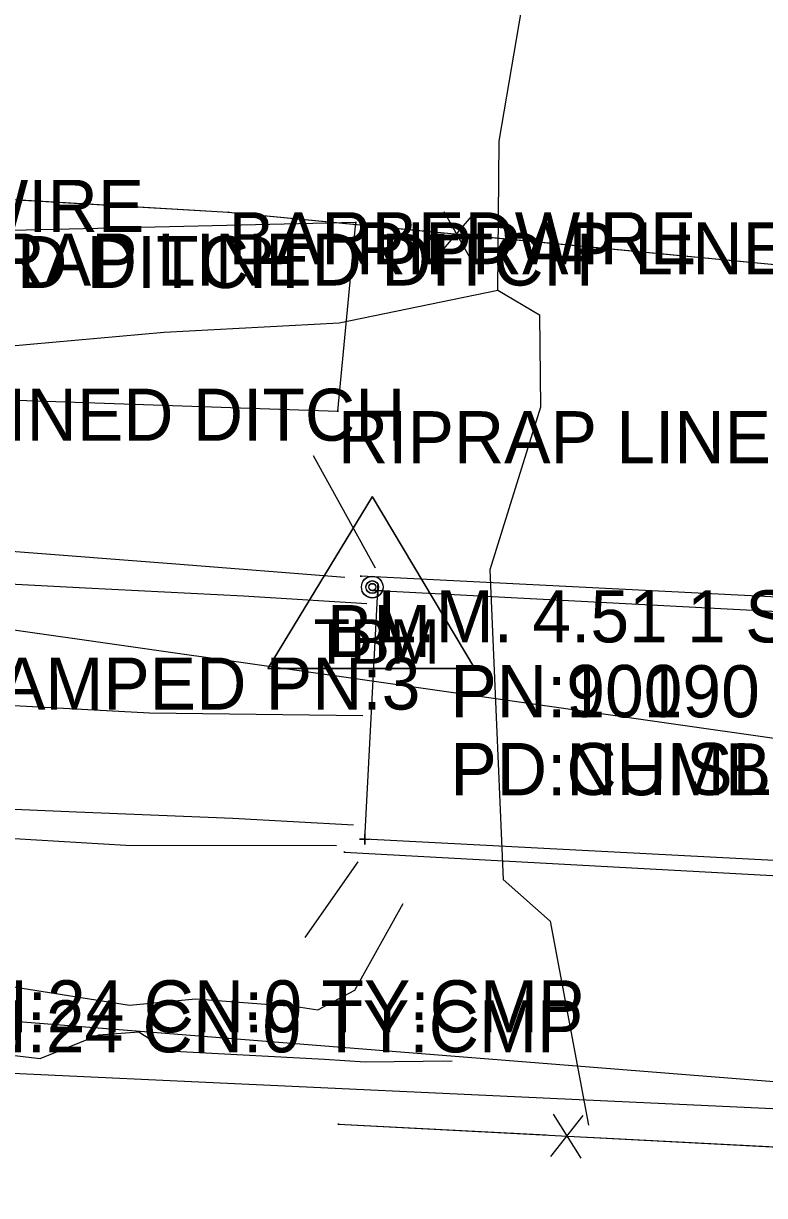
# Model space of a CAD drawing. Extents: x 675481 to 678499, y 212715 to 215285.
# Drawn here: x 676966.8 to 677038, y 214637 to 214749.7 of the extents above; entities that cross this region are included whole.
import ezdxf

# ---------------------------------------------------------------- set-up
doc = ezdxf.new("R2010")
doc.units = 0
for name, color, linetype in [('S_BASELINE', 7, 'Continuous'), ('S_BRIDGE', 7, 'Continuous'), ('S_BRIDGE_ANNOT', 7, 'Continuous'), ('S_DITCHLINE', 7, 'Continuous'), ('S_EDGE_PAVEMENT', 7, 'Continuous'), ('S_FENCE', 7, 'Continuous'), ('S_FENCE_ANNOT', 7, 'Continuous'), ('S_FIBER_OPTIC_CABLE', 7, 'Continuous'), ('S_GRD_PT_SYM', 7, 'Continuous'), ('S_GUARDRAIL', 7, 'Continuous'), ('S_HEADWALL', 7, 'Continuous'), ('S_MISC_TOPO_POINT', 7, 'Continuous'), ('S_MSC_PT_SYM', 7, 'Continuous'), ('S_PAVEMENT_CROWN', 7, 'Continuous'), ('S_PRIMARY_CTL', 7, 'Continuous'), ('S_PRIMARY_CTL_ANNOT', 7, 'Continuous'), ('S_RDW_PT_SYM', 7, 'Continuous'), ('S_SHOULDER', 7, 'Continuous'), ('S_SIDE_DRAIN_ANNOT', 7, 'Continuous'), ('S_STR_PT_SYM', 7, 'Continuous'), ('S_STREAM', 7, 'Continuous')]:
    doc.layers.add(name, color=color, linetype=linetype)

msp = doc.modelspace()

# ---------------------------------------------------------------- linework, layer by layer
at = {"layer": 'S_BASELINE'}
msp.add_line((676879.32, 214703.75), (677859.18, 214564.08), dxfattribs=at)
at = {"layer": 'S_BRIDGE'}
for p, q in [((676999.6, 214671.29), (677000.85, 214695.21)), ((677000.85, 214695.21), (677040.83, 214693.09)), ((677039.56, 214669.22), (676999.6, 214671.29))]:
    msp.add_line(p, q, dxfattribs=at)
at = {"layer": 'S_DITCHLINE'}
for points in [[(676941.29, 214657.02), (676947.35, 214657.44), (676951.26, 214656.86), (676952.87, 214657.58), (676966.09, 214657.07), (676977, 214655.34), (676983.34, 214655.95), (676993.03, 214655.21), (676995.09, 214654.89), (676998.66, 214656.78), (677003.31, 214665.09)], [(676941.3, 214657), (676940.79, 214653.2), (676935.57, 214649.83), (676934.83, 214644.8), (676942.35, 214650.64), (676951.66, 214651.63), (676952.82, 214652.02), (676968.41, 214650.19), (676974.05, 214652.49), (676977.88, 214652.75), (676980.7, 214650.93), (676995.74, 214650.15), (676999.63, 214649.87), (677008, 214649.99)]]:
    msp.add_lwpolyline(points, dxfattribs=at)
at = {"layer": 'S_EDGE_PAVEMENT'}
for points in [[(676677.25, 214711.01), (676699.88, 214710.21), (676722.5, 214709.42), (676735.45, 214708.74), (676748.41, 214708.05), (676761.36, 214707.37), (676774.32, 214706.69), (676787.27, 214706.01), (676800.23, 214705.33), (676813.18, 214704.64), (676826.14, 214703.96), (676838.77, 214703.19), (676851.4, 214702.42), (676864.03, 214701.65), (676876.65, 214700.88), (676889.28, 214700.1), (676901.91, 214699.33), (676914.54, 214698.56), (676927.17, 214697.79), (676942.37, 214697.01), (676957.56, 214696.24), (676972.76, 214695.46), (676987.95, 214694.68), (676999.79, 214693.96)], [(676676.07, 214690.47), (676698.02, 214689.27), (676719.97, 214688.08), (676733, 214687.38), (676746.03, 214686.69), (676759.06, 214685.99), (676772.1, 214685.3), (676785.13, 214684.61), (676798.16, 214683.91), (676811.19, 214683.22), (676824.22, 214682.52), (676837.04, 214681.68), (676849.87, 214680.84), (676862.69, 214680), (676875.51, 214679.16), (676888.34, 214678.31), (676901.16, 214677.47), (676913.98, 214676.63), (676926.8, 214675.79), (676941.84, 214675.17), (676956.87, 214674.55), (676971.9, 214673.93), (676986.94, 214673.32), (676998.53, 214672.68)]]:
    msp.add_lwpolyline(points, dxfattribs=at)
at = {"layer": 'S_FENCE'}
for p, q in [((676933.46, 214734.68), (676986.52, 214731.57)), ((677007.19, 214731.65), (677009.65, 214727.3)), ((676986.52, 214731.57), (677040.37, 214726.42)), ((677006.8, 214727.57), (677010.04, 214731.37)), ((677017.72, 214644.86), (677020.37, 214640.62)), ((676997.07, 214643.89), (677052.11, 214641.02)), ((677017.5, 214640.77), (677020.58, 214644.71))]:
    msp.add_line(p, q, dxfattribs=at)
for points in [[(676957.41, 214733.28), (676986.52, 214731.57)], [(676986.52, 214731.57), (677006.43, 214729.66)], [(677010.41, 214729.28), (677040.37, 214726.42)], [(676997.07, 214643.89), (677017.04, 214642.85)], [(677021.04, 214642.64), (677052.11, 214641.02)]]:
    msp.add_lwpolyline(points, dxfattribs=at)
at = {"layer": 'S_FIBER_OPTIC_CABLE'}
for p, q in [((676936.82, 214656.1), (677074.33, 214645.17)), ((676933.93, 214650.27), (677038.82, 214645.4))]:
    msp.add_line(p, q, dxfattribs=at)
at = {"layer": 'S_GRD_PT_SYM'}
for points in [[(676998.75, 214730.58), (676998.75, 214730.63), (676998.75, 214730.58), (676998.7, 214730.58), (676998.75, 214730.58), (676998.75, 214730.53), (676998.75, 214730.58), (676998.8, 214730.58)], [(676997.03, 214712.44), (676997.03, 214712.49), (676997.03, 214712.44), (676996.98, 214712.44), (676997.03, 214712.44), (676997.03, 214712.39), (676997.03, 214712.44), (676997.08, 214712.44)]]:
    msp.add_lwpolyline(points, dxfattribs=at)
at = {"layer": 'S_GUARDRAIL'}
for p, q in [((677042.56, 214694.4), (676999.23, 214696.58)), ((676997.65, 214670.04), (677041.23, 214667.66))]:
    msp.add_line(p, q, dxfattribs=at)
at = {"layer": 'S_HEADWALL'}
for points in [[(676994.64, 214708.18), (677000.59, 214697.39)], [(676998.94, 214669.12), (676993.86, 214661.84)]]:
    msp.add_lwpolyline(points, dxfattribs=at)
at = {"layer": 'S_MISC_TOPO_POINT'}
for p, q in [((676998.75, 214730.58), (676952.88, 214729.52)), ((676997.03, 214712.44), (676998.75, 214730.58)), ((676934.78, 214714.6), (676997.03, 214712.44))]:
    msp.add_line(p, q, dxfattribs=at)
at = {"layer": 'S_MSC_PT_SYM'}
for points in [[(676986.52, 214731.57), (676986.52, 214731.61), (676986.52, 214731.57), (676986.47, 214731.57), (676986.52, 214731.57), (676986.52, 214731.52), (676986.52, 214731.57), (676986.57, 214731.57)], [(676997.07, 214643.89), (676997.07, 214643.94), (676997.07, 214643.89), (676997.02, 214643.89), (676997.07, 214643.89), (676997.07, 214643.84), (676997.07, 214643.89), (676997.12, 214643.89)]]:
    msp.add_lwpolyline(points, dxfattribs=at)
at = {"layer": 'S_PAVEMENT_CROWN'}
msp.add_lwpolyline([(676676.38, 214701.07), (676698.84, 214700.19), (676721.29, 214699.32), (676734.24, 214698.53), (676747.19, 214697.75), (676760.13, 214696.97), (676773.08, 214696.19), (676786.03, 214695.41), (676798.98, 214694.63), (676811.92, 214693.85), (676824.87, 214693.07), (676837.62, 214692.22), (676850.38, 214691.37), (676863.13, 214690.52), (676875.89, 214689.66), (676888.65, 214688.81), (676901.4, 214687.96), (676914.16, 214687.11), (676926.91, 214686.26), (676939.91, 214685.55), (676952.91, 214684.85), (676965.91, 214684.15), (676978.91, 214683.45), (676999.41, 214683.17)], dxfattribs=at)
at = {"layer": 'S_PRIMARY_CTL'}
for p, q in [((677000.33, 214704.21), (676990.29, 214687.7)), ((677000.33, 214704.24), (676990.3, 214687.73)), ((677000.33, 214704.24), (677010.16, 214687.73)), ((677000.33, 214704.21), (677010.15, 214687.7)), ((676990.29, 214687.7), (677010.15, 214687.7)), ((676990.3, 214687.73), (677010.16, 214687.73))]:
    msp.add_line(p, q, dxfattribs=at)
for centre, radius in [((677000.33, 214695.51), 1.04), ((677000.33, 214695.54), 1.04), ((677000.33, 214695.54), 0.609), ((677000.33, 214695.51), 0.609), ((677000.33, 214695.51), 0.344), ((677000.33, 214695.54), 0.344)]:
    msp.add_circle(centre, radius, dxfattribs=at)
at = {"layer": 'S_RDW_PT_SYM'}
for points in [[(676999.23, 214696.58), (676999.23, 214696.63), (676999.23, 214696.58), (676999.18, 214696.58), (676999.23, 214696.58), (676999.23, 214696.53), (676999.23, 214696.58), (676999.28, 214696.58)], [(676997.65, 214670.04), (676997.65, 214670.09), (676997.65, 214670.04), (676997.6, 214670.04), (676997.65, 214670.04), (676997.65, 214669.99), (676997.65, 214670.04), (676997.7, 214670.04)]]:
    msp.add_lwpolyline(points, dxfattribs=at)
at = {"layer": 'S_SHOULDER'}
for points in [[(676678.76, 214714.1), (676700.72, 214712.83), (676722.69, 214711.55), (676735.58, 214710.91), (676748.48, 214710.26), (676761.37, 214709.61), (676774.27, 214708.96), (676787.16, 214708.31), (676800.06, 214707.66), (676812.95, 214707.01), (676825.85, 214706.36), (676838.52, 214705.61), (676851.19, 214704.86), (676863.86, 214704.11), (676876.53, 214703.36), (676889.2, 214702.61), (676901.88, 214701.86), (676914.55, 214701.12), (676927.22, 214700.37), (676946.23, 214699.69), (676965.23, 214699.02), (676981.46, 214697.75), (676997.69, 214696.47)], [(676950.8, 214672.24), (676963.73, 214671.47), (676976.65, 214670.7), (676996.9, 214670.68)]]:
    msp.add_lwpolyline(points, dxfattribs=at)
at = {"layer": 'S_STR_PT_SYM'}
for points in [[(677000.85, 214695.21), (677000.85, 214695.71), (677000.85, 214695.21), (677000.35, 214695.21), (677000.85, 214695.21), (677000.85, 214694.71), (677000.85, 214695.21), (677001.35, 214695.21)], [(676999.6, 214671.29), (676999.6, 214671.79), (676999.6, 214671.29), (676999.1, 214671.29), (676999.6, 214671.29), (676999.6, 214670.79), (676999.6, 214671.29), (677000.1, 214671.29)]]:
    msp.add_lwpolyline(points, dxfattribs=at)
at = {"layer": 'S_STREAM'}
for points in [[(676826.74, 214729.27), (676840.32, 214728.33), (676853.89, 214727.39), (676867.47, 214726.46), (676881.05, 214725.52), (676894.62, 214724.58), (676908.2, 214723.65), (676921.78, 214722.71), (676935.35, 214721.77), (676948.16, 214720.04), (676960.97, 214718.3), (676980.32, 214720.05), (676997.14, 214720.93), (677012.4, 214724.08), (677012.52, 214738.39), (677014.93, 214752.54), (677015.49, 214765.55), (677016.05, 214778.56), (677022.16, 214797.46), (677018.44, 214813.9), (677014.72, 214830.33), (677008.06, 214842.31), (677001.39, 214854.29), (677000.3, 214873.45)], [(677012.4, 214724.08), (677016.39, 214721.7), (677016.5, 214712.84), (677011.64, 214697.18), (677012.27, 214682.29), (677012.9, 214667.4), (677017.43, 214663.4), (677021.09, 214643.79)]]:
    msp.add_lwpolyline(points, dxfattribs=at)

# ---------------------------------------------------------------- texts
at = {"layer": 'S_BRIDGE_ANNOT'}
msp.add_text('L.M. 4.51 1 SPAN CONC DECK', height=5, dxfattribs=at).set_placement((677000.85, 214690.21))
at = {"layer": 'S_FENCE_ANNOT'}
for p in [(676933.46, 214729.68), (676986.52, 214726.57)]:
    msp.add_text('BARBEDWIRE', height=5, dxfattribs=at).set_placement(p)
at = {"layer": 'S_MISC_TOPO_POINT'}
for p in [(676998.75, 214725.58), (676952.88, 214724.52), (676924.58, 214724.28), (676934.78, 214709.6), (676997.03, 214707.44)]:
    msp.add_text('RIPRAP LINED DITCH', height=5, dxfattribs=at).set_placement(p)
at = {"layer": 'S_PRIMARY_CTL'}
for s, height, p in [('BM', 5, (676995.96, 214688.8)), ('TBM', 4.287, (676994.68, 214688.15))]:
    msp.add_text(s, height=height, rotation=360, dxfattribs=at).set_placement(p)
at = {"layer": 'S_PRIMARY_CTL_ANNOT'}
for s, p in [('PD:STD ARDOT MON STAMPED PN:3', (676886.82, 214683.75)), ('PN:10190', (677007.83, 214683.01)), ('PN:900', (677007.83, 214683.04)), ('PD:NUMBER 900 NW CURB STR M1470', (677007.83, 214675.51)), ('PD:CHISLED SQR IN W BR CORNR', (677007.83, 214675.54))]:
    msp.add_text(s, height=5, dxfattribs=at).set_placement(p)
at = {"layer": 'S_SIDE_DRAIN_ANNOT'}
for p in [(676916.3, 214652.72), (676916.2, 214650.79)]:
    msp.add_text('WD:21 HT:15 LN:24 CN:0 TY:CMP', height=5, dxfattribs=at).set_placement(p)

doc.saveas('drawing.dxf')
